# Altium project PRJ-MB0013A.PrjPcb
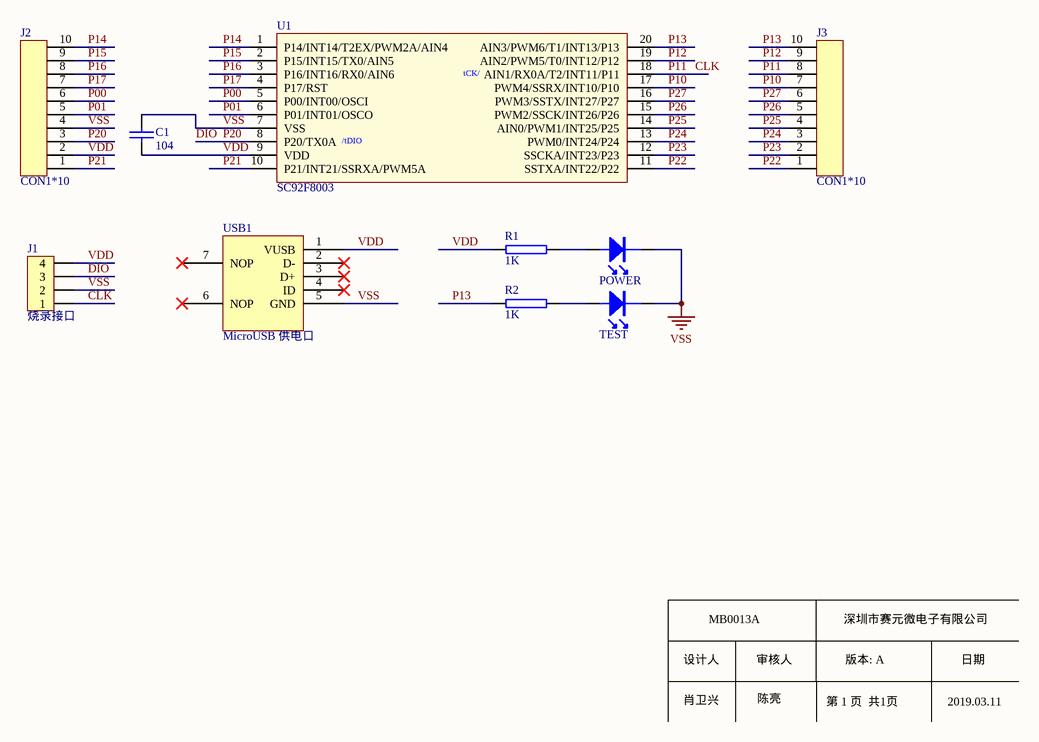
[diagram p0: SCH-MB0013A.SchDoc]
1 sheet, 10 parts. Net scope: global (net labels, ports and power ports of the same name join across sheets).
Board file: PCB-MB0013A.PcbDoc

## Sheet SCH-MB0013A.SchDoc
size A4

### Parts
C1  104  [C0805]
J1  烧录接口  [CON1*4(P=2.54)]
J2  CON1*10  [CON1*10(P=2.54)]
J3  CON1*10  [CON1*10(P=2.54)]
LED1  POWER  [LED0805]
LED2  TEST  [LED0805]
R1  1K  [R0805]
R2  1K  [R0805]
U1  SC92F8003  [TSSOP20s]
USB1  MicroUSB 供电口  [microusb]

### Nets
VSS: C1.2 J1.2 J2.4 LED1.2 LED2.2 U1.7(VSS) USB1.5(GND)
CLK: J1.1 J3.8 U1.18(AIN1/RX0A/T2/INT11/P11)  [also labelled P11]
DIO: J1.3 J2.3 U1.8(P20/TX0A)  [also labelled P20]
P00: J2.6 U1.5(P00/INT00/OSCI)
P01: J2.5 U1.6(P01/INT01/OSCO)
P10: J3.7 U1.17(PWM4/SSRX/INT10/P10)
P12: J3.9 U1.19(AIN2/PWM5/T0/INT12/P12)
P13: J3.10 R2.1 U1.20(AIN3/PWM6/T1/INT13/P13)
P14: J2.10 U1.1(P14/INT14/T2EX/PWM2A/AIN4)
P15: J2.9 U1.2(P15/INT15/TX0/AIN5)
P16: J2.8 U1.3(P16/INT16/RX0/AIN6)
P17: J2.7 U1.4(P17/RST)
P21: J2.1 U1.10(P21/INT21/SSRXA/PWM5A)
P22: J3.1 U1.11(SSTXA/INT22/P22)
P23: J3.2 U1.12(SSCKA/INT23/P23)
P24: J3.3 U1.13(PWM0/INT24/P24)
P25: J3.4 U1.14(AIN0/PWM1/INT25/P25)
P26: J3.5 U1.15(PWM2/SSCK/INT26/P26)
P27: J3.6 U1.16(PWM3/SSTX/INT27/P27)
VDD: C1.1 J1.4 J2.2 R1.2 U1.9(VDD) USB1.1(VUSB)
NetLED1_1: LED1.1 R1.1
NetLED2_1: LED2.1 R2.2

Not connected (* = marked no-connect by the designer): USB1 2(D-)* 3(D+)* 4(ID)* 6(NOP)* 7(NOP)*

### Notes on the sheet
- MB0013A
- 深圳市赛元微电子有限公司
- 设计人
- 肖卫兴
- 审核人
- 陈亮
- 第 1 页  共1页
- 版本: A
- 2019.03.11
- 日期

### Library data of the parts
C1 = CAP1: 贴片电容
J1 = CON1*4
LED1 LED2 = LED
R1 R2 = R0805: 功率: 1/8W
U1 = SC92F8003: 电压:2.4V-5.5V;ROM:16KB;RAM:256B+256B;16/8/4/1.33MHz
USB1 = MicroUSB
